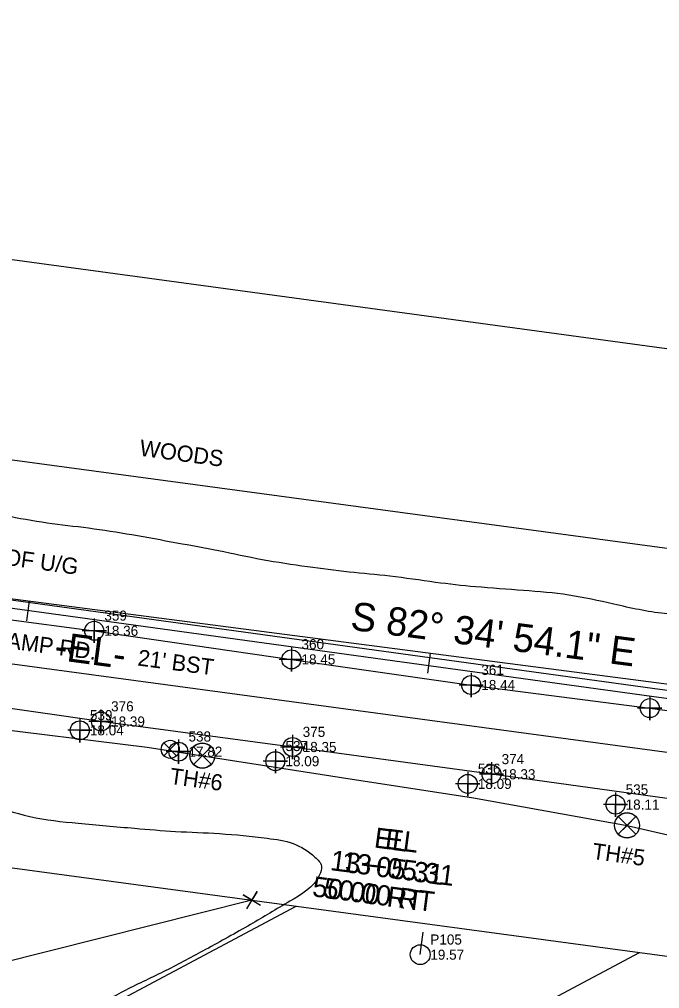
# Model space of a CAD drawing. Extents: x 2627243 to 2636458, y 566398 to 571062.
# Drawn here: x 2634311.2 to 2634469.5, y 569061.3 to 569301 of the extents above; entities that cross this region are included whole.
import ezdxf

# ---------------------------------------------------------------- set-up
doc = ezdxf.new("R2010")
doc.units = 0
for name, color, linetype in [('COGO Default Chain', 7, 'Continuous'), ('Exist Horizontal Alignment', 7, 'Continuous'), ('Exist Horizontal Alignment Direction Label', 7, 'Continuous'), ('Exist Horizontal Baseline Alignment', 7, 'Continuous'), ('Exist Horizontal Baseline Alignment Direction Label', 7, 'Continuous'), ('Exist Horizontal Baseline Alignment Tick small', 7, 'Continuous'), ('Exist Hydro Jurisdictional Stream or Body of Water', 7, 'Continuous'), ('Exist Property Corner CELL', 7, 'Continuous'), ('Exist Property Line', 7, 'Continuous'), ('Exist Right of Way Easement Line', 7, 'Continuous'), ('Exist Right of Way Line', 7, 'Continuous'), ('Exist Roads EOP', 7, 'Continuous'), ('Exist Roads EOP Cogo Elevation', 7, 'Continuous'), ('Exist Roads EOP Cogo Number', 7, 'Continuous'), ('Exist Roads EOP Cogo Point CELL', 7, 'Continuous'), ('Exist Roads EOP Text', 7, 'Continuous'), ('Exist Utilities Power Pole CELL', 7, 'Continuous'), ('Exist Utilities Power Pole Cogo Elevation', 7, 'Continuous'), ('Exist Utilities Power Pole Cogo Number', 7, 'Continuous'), ('Exist Utilities Telephone UG Cable', 7, 'Continuous'), ('Exist Utilities Telephone UG Cable Text', 7, 'Continuous'), ('Exist Utilities Water Test Hole SUE CELL', 7, 'Continuous'), ('Exist Utilities Water Test Hole SUE Text', 7, 'Continuous'), ('Exist Utilities Water UG Line Cogo Elevation', 7, 'Continuous'), ('Exist Utilities Water UG Line Cogo Number', 7, 'Continuous'), ('Exist Utilities Water UG Line Cogo Point CELL', 7, 'Continuous'), ('Exist Utilities Water UG Line SUE', 7, 'Continuous'), ('Exist Utilities Water Valve CELL', 7, 'Continuous'), ('Exist Vegetation Woods Line', 7, 'Continuous'), ('Exist Vegetation Woods Line Text', 7, 'Continuous'), ('Scratch_Level_1', 7, 'Continuous'), ('Scratch_Level_2', 7, 'Continuous')]:
    doc.layers.add(name, color=color, linetype=linetype)

# ---------------------------------------------------------------- blocks, each defined once
blk = doc.blocks.new('EXIST ROADS EOP COGO POINT')
at = {"layer": 'Exist Roads EOP Cogo Point CELL'}
blk.add_lwpolyline([(0, 0.06), (0, -0.06), (0, 0), (0.06, 0), (-0.06, 0)], dxfattribs=at)
blk.add_circle((0, 0), 0.0469, dxfattribs=at)
blk = doc.blocks.new('EXIST UTILITIES POWER POLE')
at = {"layer": 'Exist Utilities Power Pole CELL'}
for q in [(0, 0.1125), (0, 0)]:
    blk.add_line((0, 0), q, dxfattribs=at)
blk.add_circle((0, 0), 0.049, dxfattribs=at)
blk = doc.blocks.new('EXIST UTILITIES WATER UG LINE COGO POINT')
at = {"layer": 'Exist Utilities Water UG Line Cogo Point CELL'}
blk.add_lwpolyline([(0, 0.06), (0, -0.06), (0, 0), (0.06, 0), (-0.06, 0)], dxfattribs=at)
blk.add_circle((0, 0), 0.0469, dxfattribs=at)

msp = doc.modelspace()

# ---------------------------------------------------------------- linework, layer by layer
at = {"layer": 'COGO Default Chain'}
msp.add_line((2634072.78, 569173.54), (2634872.74, 569065.7), dxfattribs=at)
msp.add_line((2634072.78, 569173.54), (2634872.74, 569065.7), dxfattribs=at)
at = {"layer": 'Exist Horizontal Alignment'}
msp.add_line((2634072.78, 569173.54), (2634872.74, 569065.7), dxfattribs=at)
at = {"layer": 'Exist Horizontal Baseline Alignment'}
msp.add_line((2634115.27, 569183.03), (2634680.61, 569109.43), dxfattribs=at)
at = {"layer": 'Exist Horizontal Baseline Alignment Tick small'}
for p, q in [((2634313.59, 569157.21), (2634312.95, 569152.25)), ((2634412.76, 569144.3), (2634412.11, 569139.34))]:
    msp.add_line(p, q, dxfattribs=at)
at = {"layer": 'Exist Hydro Jurisdictional Stream or Body of Water'}
for points in [[(2634439.26, 569571.19), (2634439.59, 569567.51), (2634440.97, 569553.79), (2634439.58, 569543.4), (2634438.39, 569535.28), (2634439.25, 569529.24), (2634442.01, 569520.57), (2634446.12, 569510.93), (2634451.13, 569500.07), (2634455.3, 569490.19), (2634459.75, 569478.75), (2634463.32, 569469.08), (2634467.91, 569457.55), (2634471.65, 569447.03), (2634476.22, 569436.22), (2634476.14, 569426), (2634480.26, 569412.99), (2634486.48, 569403.77), (2634490.89, 569393.2), (2634498.99, 569385.5), (2634504, 569375.33), (2634510.06, 569363.23), (2634514.79, 569352.59), (2634523.21, 569338.71), (2634529.54, 569329.23), (2634534.99, 569318.17), (2634540.14, 569307.26), (2634544.47, 569296.7), (2634548.36, 569286.33), (2634552.93, 569273.85), (2634556.48, 569264.02), (2634560.09, 569255.14), (2634586.41, 569214.21)], [(2634396.85, 569568.94), (2634398.53, 569550.39), (2634398.58, 569537.64), (2634396.23, 569521.18), (2634398.28, 569504.33), (2634403.52, 569492.03), (2634410.28, 569482.87), (2634414.25, 569474.82), (2634418.81, 569464.96), (2634429.18, 569444.89), (2634434.17, 569431.88), (2634437.87, 569422.9), (2634437.78, 569407.05), (2634442.18, 569396.54), (2634447.37, 569385.08), (2634452.56, 569374.37), (2634457.16, 569364.96), (2634462.27, 569354.6), (2634467.92, 569343.32), (2634473.41, 569330.96), (2634483.89, 569313.67), (2634489.1, 569305.88), (2634493.02, 569297.93), (2634497.48, 569288.47), (2634501.09, 569279.67), (2634504.67, 569270.14), (2634509.14, 569257.93), (2634512.97, 569247.32), (2634517.16, 569237.03), (2634535.26, 569188.38)]]:
    msp.add_spline(points, degree=3, dxfattribs=at)
at = {"layer": 'Exist Property Corner CELL'}
msp.add_line((2634368.67, 569083.2), (2634368.67, 569083.2), dxfattribs=at)
msp.add_lwpolyline([(2634367.39, 569081.06), (2634369.95, 569085.35), (2634368.67, 569083.2), (2634366.52, 569084.48), (2634370.82, 569081.92)], dxfattribs=at)
at = {"layer": 'Exist Property Line'}
msp.add_line((2634368.67, 569083.2), (2633567.02, 568881.75), dxfattribs=at)
at = {"layer": 'Exist Right of Way Easement Line'}
for points in [[(2633144.61, 568565.55), (2634113.14, 568939.71), (2634379.66, 569081.72)], [(2633136.66, 568508.88), (2634133.98, 568894.16), (2634464.52, 569070.28)]]:
    msp.add_lwpolyline(points, dxfattribs=at)
at = {"layer": 'Exist Right of Way Line'}
for p, q in [((2632427.74, 569445.76), (2634879.42, 569115.25)), ((2632403.14, 569348.18), (2634866.06, 569016.15))]:
    msp.add_line(p, q, dxfattribs=at)
at = {"layer": 'Exist Roads EOP'}
for points in [[(2634098.59, 569180.52), (2634142.79, 569174.77), (2634190.95, 569168.56), (2634239.66, 569162.02), (2634284.94, 569155.78), (2634329.7, 569149.83), (2634378.45, 569142.75), (2634422.9, 569136.41), (2634467.06, 569130.69), (2634503.95, 569125.77)], [(2634476.75, 569107.62), (2634427.93, 569114.34), (2634378.74, 569121.08), (2634331.37, 569127.39), (2634284.17, 569134.17), (2634236.53, 569140.28), (2634193.58, 569145.86), (2634150.29, 569151.68), (2634114.34, 569156.93), (2634090.06, 569160.3)]]:
    msp.add_lwpolyline(points, dxfattribs=at)
at = {"layer": 'Exist Utilities Telephone UG Cable'}
for points in [[(2633874.52, 569217.37), (2634467.74, 569135.65), (2634529.44, 569127.34), (2634533.2, 569140.37)], [(2633874.24, 569215.39), (2634467.47, 569133.66), (2634530.89, 569125.13), (2634535.28, 569140.37)]]:
    msp.add_lwpolyline(points, dxfattribs=at)
at = {"layer": 'Exist Utilities Water Test Hole SUE CELL'}
for points in [[(2634354.26, 569116.76), (2634358.6, 569121.12), (2634356.43, 569118.94), (2634358.61, 569116.81), (2634354.23, 569121.12)], [(2634354.24, 569121.11), (2634356.44, 569118.95), (2634356.44, 569118.95), (2634358.6, 569121.12), (2634358.6, 569121.12)], [(2634358.62, 569116.79), (2634358.61, 569116.81), (2634356.43, 569118.94), (2634354.26, 569116.76)], [(2634459.28, 569099.51), (2634463.62, 569103.87), (2634461.45, 569101.69), (2634463.62, 569099.55), (2634459.25, 569103.87)], [(2634459.26, 569103.86), (2634461.45, 569101.69), (2634461.45, 569101.69), (2634463.62, 569103.87), (2634463.62, 569103.87)], [(2634463.64, 569099.54), (2634463.62, 569099.55), (2634461.45, 569101.69), (2634459.28, 569099.51)]]:
    msp.add_lwpolyline(points, dxfattribs=at)
for centre in [(2634356.43, 569118.95), (2634461.44, 569101.69)]:
    msp.add_circle(centre, 3.08, dxfattribs=at)
for centre, start, end in [((2634356.43, 569118.95), 45, 135.3289), ((2634356.43, 569118.95), 225.1651, 315.4953), ((2634461.44, 569101.69), 45, 135.3289), ((2634461.44, 569101.69), 225.1651, 315.4953)]:
    msp.add_arc(centre, 3.08, start, end, dxfattribs=at)
at = {"layer": 'Exist Utilities Water UG Line SUE'}
msp.add_lwpolyline([(2633936.66, 569175.83), (2633996.02, 569168.25), (2634028.2, 569163.11), (2634063.1, 569158.09), (2634109, 569151.22), (2634141.82, 569147), (2634174.42, 569142.3), (2634205.44, 569138.19), (2634236.43, 569134.33), (2634269.33, 569130.22), (2634299.96, 569126.31), (2634342.79, 569121.04), (2634390.86, 569113.57), (2634423.51, 569108.48), (2634461.44, 569101.69), (2634487.67, 569095.65), (2634491.94, 569094.67)], dxfattribs=at)
at = {"layer": 'Exist Utilities Water Valve CELL'}
msp.add_lwpolyline([(2634350.07, 569122.08), (2634346.92, 569118.93), (2634348.49, 569120.5), (2634350.07, 569118.93), (2634346.92, 569122.08)], dxfattribs=at)
msp.add_circle((2634348.49, 569120.5), 2.23, dxfattribs=at)
at = {"layer": 'Exist Vegetation Woods Line'}
for points in [[(2634392.31, 569564.87), (2634393.36, 569560.61), (2634394.35, 569549.31), (2634394.02, 569537.8), (2634392.82, 569525.73), (2634391.57, 569515.69), (2634392.51, 569504.78), (2634393.84, 569497.81), (2634395.6, 569492.76), (2634400.87, 569483.76), (2634407.47, 569473.34), (2634412.27, 569464.46), (2634417.66, 569454.31), (2634422.98, 569444.93), (2634428.51, 569434.24), (2634432.46, 569422.15), (2634434.6, 569410.97), (2634437.5, 569399.24), (2634441.27, 569389.7), (2634445.91, 569380.1), (2634449.77, 569370.42), (2634453.45, 569361.03), (2634457.81, 569351.87), (2634462.97, 569341.77), (2634468.24, 569330.51), (2634473.09, 569319.6), (2634478, 569309.56), (2634483.7, 569297.95), (2634488.93, 569288.72), (2634494.9, 569280.58), (2634497.98, 569276.36), (2634502.49, 569265.65), (2634505.9, 569255.07), (2634509.62, 569245.29), (2634513.83, 569236.04), (2634518.32, 569226.34), (2634522.84, 569215.63), (2634527.24, 569204.44), (2634530.96, 569194.67), (2634535.09, 569183.92), (2634539.49, 569174.37), (2634545.99, 569164.1), (2634548.89, 569158.54), (2634550.41, 569149.63), (2634549.93, 569147.48), (2634547.91, 569145.79), (2634540.85, 569144.61), (2634527.62, 569145.7), (2634516.13, 569146.64), (2634503.91, 569149.39), (2634493.18, 569152.06), (2634481.31, 569153.59), (2634470.72, 569154.09), (2634458.15, 569156.41), (2634447.07, 569158.65), (2634435.87, 569159.79), (2634423.99, 569160.7), (2634414.05, 569161.8), (2634402.81, 569163.32), (2634392.71, 569164.33), (2634382.43, 569165.64), (2634371.24, 569167.4), (2634360.41, 569169.59), (2634350.14, 569171.52), (2634339.01, 569173.52), (2634328.3, 569175.17), (2634318.02, 569176.48), (2634307.61, 569178.32), (2634296.97, 569180.83), (2634285.8, 569183.22), (2634274.52, 569185.13), (2634263.24, 569187.04), (2634253.16, 569188.67), (2634241.65, 569190.64), (2634229.63, 569192.08), (2634218.43, 569193.21), (2634208.08, 569193.65), (2634195, 569194.83), (2634183.87, 569196.83), (2634172.69, 569198.59), (2634159.53, 569200.55), (2634149.16, 569202), (2634139.17, 569203.49), (2634124.43, 569205.67), (2634114.28, 569206.44), (2634101.37, 569206.7), (2634089.86, 569207.03), (2634085.09, 569207.09)], [(2634093.87, 569134.75), (2634106.43, 569134.06), (2634118.11, 569132.82), (2634130, 569130.27), (2634140.74, 569128.23), (2634153.79, 569125.8), (2634166.82, 569124.38), (2634179.77, 569123.73), (2634192.36, 569122.66), (2634205.1, 569121.06), (2634217.77, 569119.21), (2634230.56, 569117.85), (2634242.15, 569116.75), (2634253.44, 569115.47), (2634265.05, 569113.36), (2634277.1, 569111.53), (2634288.67, 569109.81), (2634302.77, 569107.02), (2634313.78, 569103.91), (2634325.74, 569102.23), (2634339.68, 569100.98), (2634349.83, 569100.21), (2634360.66, 569099.66), (2634372.49, 569098.51), (2634378.87, 569097.2), (2634384.28, 569093.85), (2634385.91, 569091.59), (2634385.43, 569089.43), (2634378.04, 569082.91), (2634368.32, 569077.17), (2634357.23, 569070.98), (2634347.37, 569065.77), (2634337.48, 569060.94), (2634328.3, 569055.96), (2634317.8, 569050.14), (2634308.56, 569044.91), (2634298.75, 569039.31), (2634288.23, 569032.87), (2634279.15, 569027.74), (2634269.03, 569021.95), (2634258.09, 569015.85), (2634247.79, 569010.37), (2634237.63, 569004.34), (2634226.73, 568997.86), (2634217.4, 568992.78), (2634205.37, 568987.43), (2634193.81, 568983.61), (2634182.73, 568979.68), (2634172.35, 568974.97), (2634163.23, 568970.22), (2634151.39, 568964.58), (2634141.36, 568960.29), (2634131.29, 568956.38), (2634119.81, 568951.79), (2634108.32, 568947.2), (2634098.2, 568943.05), (2634088.47, 568938.95), (2634078.35, 568934.8), (2634068.35, 568931.77), (2634063.32, 568931.26), (2634055.97, 568932.16), (2634053.38, 568930.73), (2634046.17, 568923.28), (2634037.44, 568916.94), (2634027.05, 568911.6), (2634017.89, 568907.24), (2634008.14, 568902.51)], [(2634038.3, 568858.08), (2634049.51, 568861.48), (2634056.44, 568863.19), (2634065.7, 568867.4), (2634077.1, 568872.77), (2634086.23, 568877.51), (2634096.46, 568882.14), (2634106.93, 568886.71), (2634118.17, 568891.35), (2634129.29, 568894.89), (2634140.88, 568899.97), (2634152.43, 568905.43), (2634162.62, 568910.43), (2634173.6, 568916.15), (2634183.27, 568921.65), (2634193.29, 568927.58), (2634201.99, 568932.67), (2634213.37, 568939.05), (2634224.54, 568944.47), (2634234.38, 568949.05), (2634246.47, 568953.01), (2634257.78, 568956.25), (2634259.95, 568956.4), (2634271.27, 568960.27), (2634281.46, 568965.28), (2634292.25, 568971.29), (2634302.02, 568976.64), (2634311.64, 568981.91), (2634323.6, 568988.66), (2634333.53, 568994.73), (2634343.88, 569000.46), (2634352.97, 569005.59), (2634362.43, 569010.14), (2634372.97, 569013.93), (2634384.91, 569017.16), (2634395.4, 569020.72), (2634404.6, 569024.69), (2634414.1, 569028.85), (2634426.66, 569034.33), (2634435.96, 569038.16), (2634445.44, 569041.69), (2634456.98, 569044.89), (2634470.18, 569048.72), (2634483.1, 569052.99), (2634494.92, 569055.74), (2634502.44, 569055.56), (2634512.78, 569056.76), (2634516.97, 569056.95), (2634521.24, 569058), (2634531.71, 569062.57), (2634544.92, 569067.03), (2634556.31, 569069.5), (2634568.39, 569071.19), (2634578.53, 569072.06), (2634583.06, 569072.04), (2634587.52, 569071.17), (2634597.26, 569065.2), (2634606.15, 569058.29), (2634612.62, 569050.67), (2634619.04, 569041.16), (2634625.85, 569031.7), (2634631.94, 569022.4), (2634637.15, 569012.54), (2634643.54, 569001.79), (2634649.3, 568990.42), (2634651.92, 568979.13), (2634651.82, 568977.02), (2634654.49, 568969.87), (2634659.59, 568947.2), (2634659.87, 568942.85), (2634658.38, 568932.87), (2634654.64, 568921.87), (2634652.1, 568909.98), (2634650.45, 568897.64), (2634648.14, 568885.69), (2634646.09, 568874.32), (2634643.13, 568863.41), (2634638.31, 568853.16), (2634632.2, 568841.69), (2634627.28, 568829.33), (2634625.24, 568818.59), (2634622.8, 568807.18), (2634618.67, 568795.52), (2634614.86, 568783.66), (2634610.42, 568771.19), (2634606.53, 568759.47), (2634602.91, 568747.32), (2634599.81, 568736.31), (2634595.85, 568726), (2634595.78, 568725.13)]]:
    msp.add_spline(points, degree=3, dxfattribs=at)
at = {"layer": 'Scratch_Level_2'}
msp.add_line((2634145.95, 569263.89), (2634907.4, 569160.42), dxfattribs=at)

# ---------------------------------------------------------------- block references
at = {"layer": 'Exist Roads EOP Cogo Point CELL', "xscale": 50, "yscale": 50}
for p in [(2634329.7, 569149.83), (2634378.45, 569142.75), (2634422.9, 569136.41), (2634467.06, 569130.69), (2634331.37, 569127.39), (2634378.74, 569121.08), (2634427.93, 569114.34)]:
    msp.add_blockref('EXIST ROADS EOP COGO POINT', p, dxfattribs=at)
at = {"layer": 'Exist Utilities Power Pole CELL', "xscale": 49.99999999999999, "yscale": 50, "rotation": -7.677818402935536}
msp.add_blockref('EXIST UTILITIES POWER POLE', (2634410.3, 569069.72), dxfattribs=at)
at = {"layer": 'Exist Utilities Water UG Line Cogo Point CELL', "xscale": 50, "yscale": 50}
for p in [(2634326.13, 569125.21), (2634350.5, 569119.93), (2634374.48, 569117.57), (2634422.05, 569111.96), (2634458.59, 569106.83)]:
    msp.add_blockref('EXIST UTILITIES WATER UG LINE COGO POINT', p, dxfattribs=at)

# ---------------------------------------------------------------- texts
at = {"layer": 'Exist Horizontal Alignment Direction Label'}
msp.add_text('-EL-', height=7, rotation=352.3222, dxfattribs=at).set_placement((2634319.57, 569142.74))
at = {"layer": 'Exist Horizontal Baseline Alignment Direction Label'}
msp.add_text('S 82%%d 34\' 54.1" E', height=7, rotation=352.5817, dxfattribs=at).set_placement((2634392.83, 569150.12))
at = {"layer": 'Exist Roads EOP Cogo Elevation'}
for s, p in [('18.36', (2634332.2, 569148.58)), ('18.45', (2634380.95, 569141.5)), ('18.44', (2634425.4, 569135.16)), ('18.39', (2634333.87, 569126.14)), ('18.35', (2634381.24, 569119.83)), ('18.33', (2634430.43, 569113.09))]:
    msp.add_text(s, height=2.5, dxfattribs=at).set_placement(p)
at = {"layer": 'Exist Roads EOP Cogo Number'}
for s, p in [('359', (2634332.2, 569152.33)), ('360', (2634380.95, 569145.25)), ('361', (2634425.4, 569138.91)), ('376', (2634333.87, 569129.89)), ('375', (2634381.24, 569123.58)), ('374', (2634430.43, 569116.84))]:
    msp.add_text(s, height=2.5, dxfattribs=at).set_placement(p)
at = {"layer": 'Exist Roads EOP Text'}
msp.add_text("SR 1003   TUNSTALL SWAMP RD.       21' BST", height=4, rotation=352.5085, dxfattribs=at).set_placement((2634245.68, 569153.7))
at = {"layer": 'Exist Utilities Power Pole Cogo Elevation'}
msp.add_text('19.57', height=2.5, dxfattribs=at).set_placement((2634412.8, 569068.47))
at = {"layer": 'Exist Utilities Power Pole Cogo Number'}
msp.add_text('P105', height=2.5, dxfattribs=at).set_placement((2634412.8, 569072.22))
at = {"layer": 'Exist Utilities Telephone UG Cable Text'}
msp.add_text('APPROXIMATE LOCATION OF U/G', height=4, rotation=352.1563, dxfattribs=at).set_placement((2634238.93, 569175.59))
at = {"layer": 'Exist Utilities Water Test Hole SUE Text'}
for s, p in [('TH#6', (2634348.2, 569111.99)), ('TH#5', (2634452.63, 569093.42))]:
    msp.add_text(s, height=4, rotation=352.1209, dxfattribs=at).set_placement(p)
at = {"layer": 'Exist Utilities Water UG Line Cogo Elevation'}
for s, p in [('18.04', (2634328.63, 569123.96)), ('17.82', (2634353, 569118.68)), ('18.09', (2634376.98, 569116.32)), ('18.09', (2634424.55, 569110.71)), ('18.11', (2634461.1, 569105.58))]:
    msp.add_text(s, height=2.5, dxfattribs=at).set_placement(p)
at = {"layer": 'Exist Utilities Water UG Line Cogo Number'}
for s, p in [('539', (2634328.63, 569127.71)), ('538', (2634353, 569122.43)), ('537', (2634376.98, 569120.07)), ('536', (2634424.55, 569114.46)), ('535', (2634461.1, 569109.33))]:
    msp.add_text(s, height=2.5, dxfattribs=at).set_placement(p)
at = {"layer": 'Exist Vegetation Woods Line Text'}
msp.add_text('WOODS', height=4, rotation=352.3222, dxfattribs=at).set_placement((2634340.73, 569193.15))
at = {"layer": 'Scratch_Level_1'}
for s, p in [('EL', (2634398.72, 569096.26)), ('13+05.31', (2634387.87, 569090.66)), ('50.00 RT', (2634383.43, 569084.19))]:
    msp.add_text(s, height=5, rotation=352.3222, dxfattribs=at).set_placement(p)
at = {"layer": 'Scratch_Level_2'}
for s, p in [('EL', (2634401.41, 569095.96)), ('13+05.31', (2634390.59, 569090.31)), ('50.00 RT', (2634386.17, 569083.83))]:
    msp.add_text(s, height=5, rotation=352.5817, dxfattribs=at).set_placement(p)

doc.saveas('drawing.dxf')
